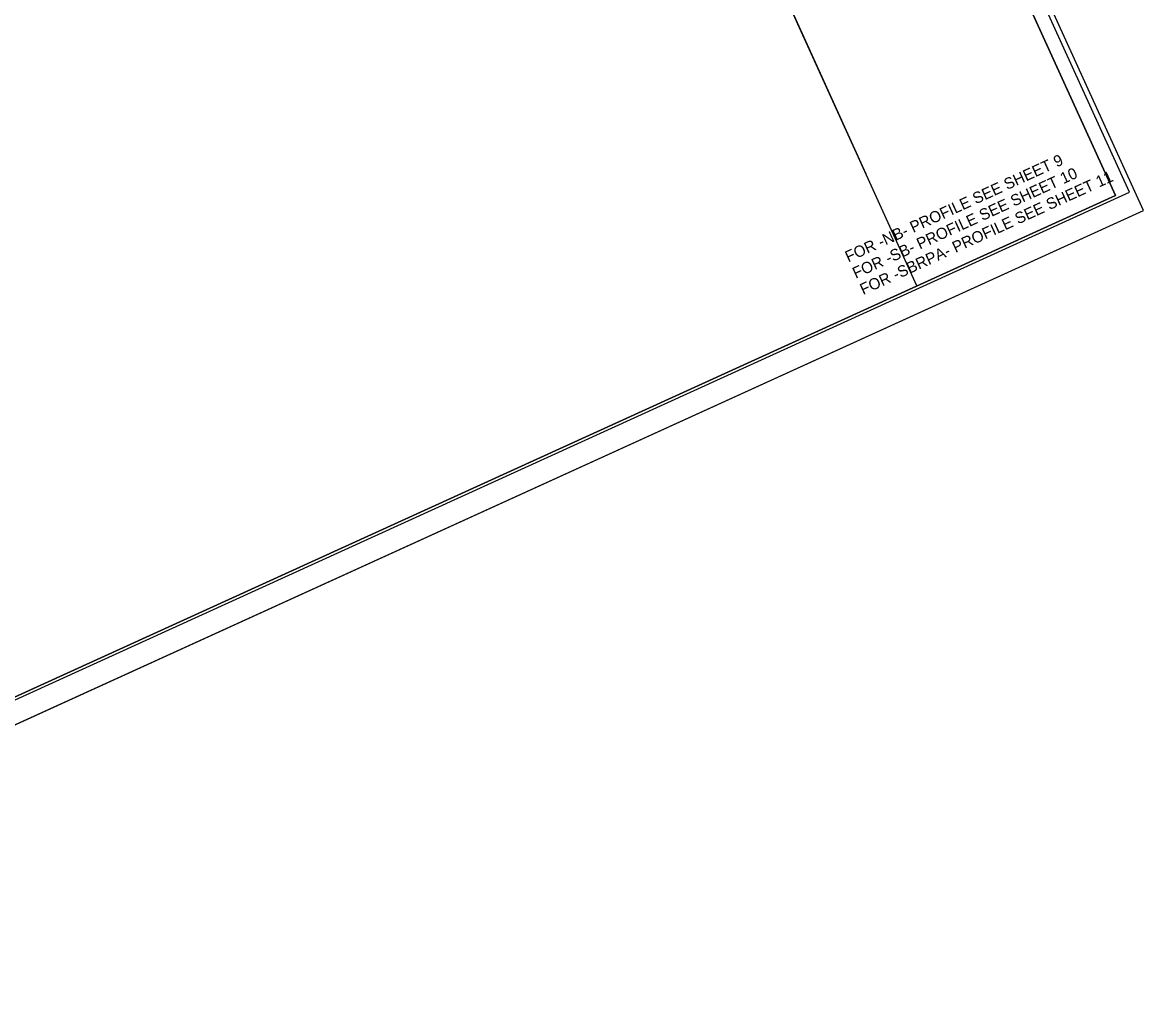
# Model space of a CAD drawing. Extents: x 2246788 to 2248774, y 662010 to 663780.
# Drawn here: x 2247781 to 2248774, y 662010 to 662875 of the extents above; entities that cross this region are included whole.
import ezdxf

# ---------------------------------------------------------------- set-up
doc = ezdxf.new("R2010")
doc.units = 0
for name, color, linetype in [('Matchline', 7, 'Continuous'), ('Prop Dimension', 7, 'Continuous'), ('Sheet Clip Boundary CELL', 7, 'Continuous'), ('Sheet Cutting Line CELL', 7, 'Continuous'), ('Sheet Plan CELL', 7, 'Continuous'), ('Sheet Plan Layout CELL', 7, 'Continuous'), ('Sheet Plot Border Inside CELL', 7, 'Continuous'), ('Sheet Plot Border Outside CELL', 7, 'Continuous')]:
    doc.layers.add(name, color=color, linetype=linetype)

msp = doc.modelspace()

# ---------------------------------------------------------------- linework, layer by layer
at = {"layer": 'Matchline'}
msp.add_line((2248241.67, 663371.06), (2248527.99, 662740.75), dxfattribs=at)
at = {"layer": 'Sheet Clip Boundary CELL'}
msp.add_lwpolyline([(2248573.04, 662641.59), (2248489.82, 662824.78), (2248241.67, 663371.06), (2248234.7, 663383.7), (2248212.22, 663373.68), (2248115.54, 663587.01), (2247008.72, 663082.61), (2247356.34, 662320.42), (2247308.04, 662298.42), (2247341.49, 662224.75), (2247444.44, 662127.31)], close=True, dxfattribs=at)
at = {"layer": 'Sheet Cutting Line CELL'}
msp.add_line((2247241.92, 662010.29), (2248773.86, 662708.37), dxfattribs=at)
at = {"layer": 'Sheet Plan CELL'}
for points in [[(2248313.69, 663677.29), (2246948.69, 663055.28), (2247384.08, 662099.81), (2248749.06, 662721.8)], [(2247384.08, 662099.81), (2246948.68, 663055.25), (2248131.62, 663594.34), (2248193.86, 663457.79), (2248375.89, 663540.73), (2248749.06, 662721.8)]]:
    msp.add_lwpolyline(points, close=True, dxfattribs=at)
at = {"layer": 'Sheet Plan Layout CELL'}
msp.add_lwpolyline([(2246948.68, 663055.25), (2247384.08, 662099.81), (2248749.05, 662721.8), (2248401.35, 663484.83), (2248183.64, 663385.62), (2248095.94, 663578.07)], close=True, dxfattribs=at)
at = {"layer": 'Sheet Plot Border Inside CELL'}
msp.add_lwpolyline([(2247245.45, 662033.88), (2248761.46, 662724.71), (2248324.01, 663684.73), (2246807.99, 662993.9)], close=True, dxfattribs=at)
at = {"layer": 'Sheet Plot Border Outside CELL'}
msp.add_lwpolyline([(2247241.92, 662010.29), (2248773.86, 662708.37), (2248319.81, 663704.79), (2246787.87, 663006.71)], close=True, dxfattribs=at)

# ---------------------------------------------------------------- texts
at = {"layer": 'Prop Dimension'}
for s, p in [('FOR -NB- PROFILE SEE SHEET 9', (2248512.3, 662662.33)), ('FOR -SB- PROFILE SEE SHEET 10', (2248518.88, 662647.88)), ('FOR -SBRPA- PROFILE SEE SHEET 11', (2248525.46, 662633.45))]:
    msp.add_text(s, height=10, rotation=24.49794, dxfattribs=at).set_placement(p)

doc.saveas('drawing.dxf')
